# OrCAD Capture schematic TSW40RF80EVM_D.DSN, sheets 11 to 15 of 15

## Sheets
11 SHEET 12 - POWER SUPPLIES: size B; title: POWER SUPPLIES - CLOCK
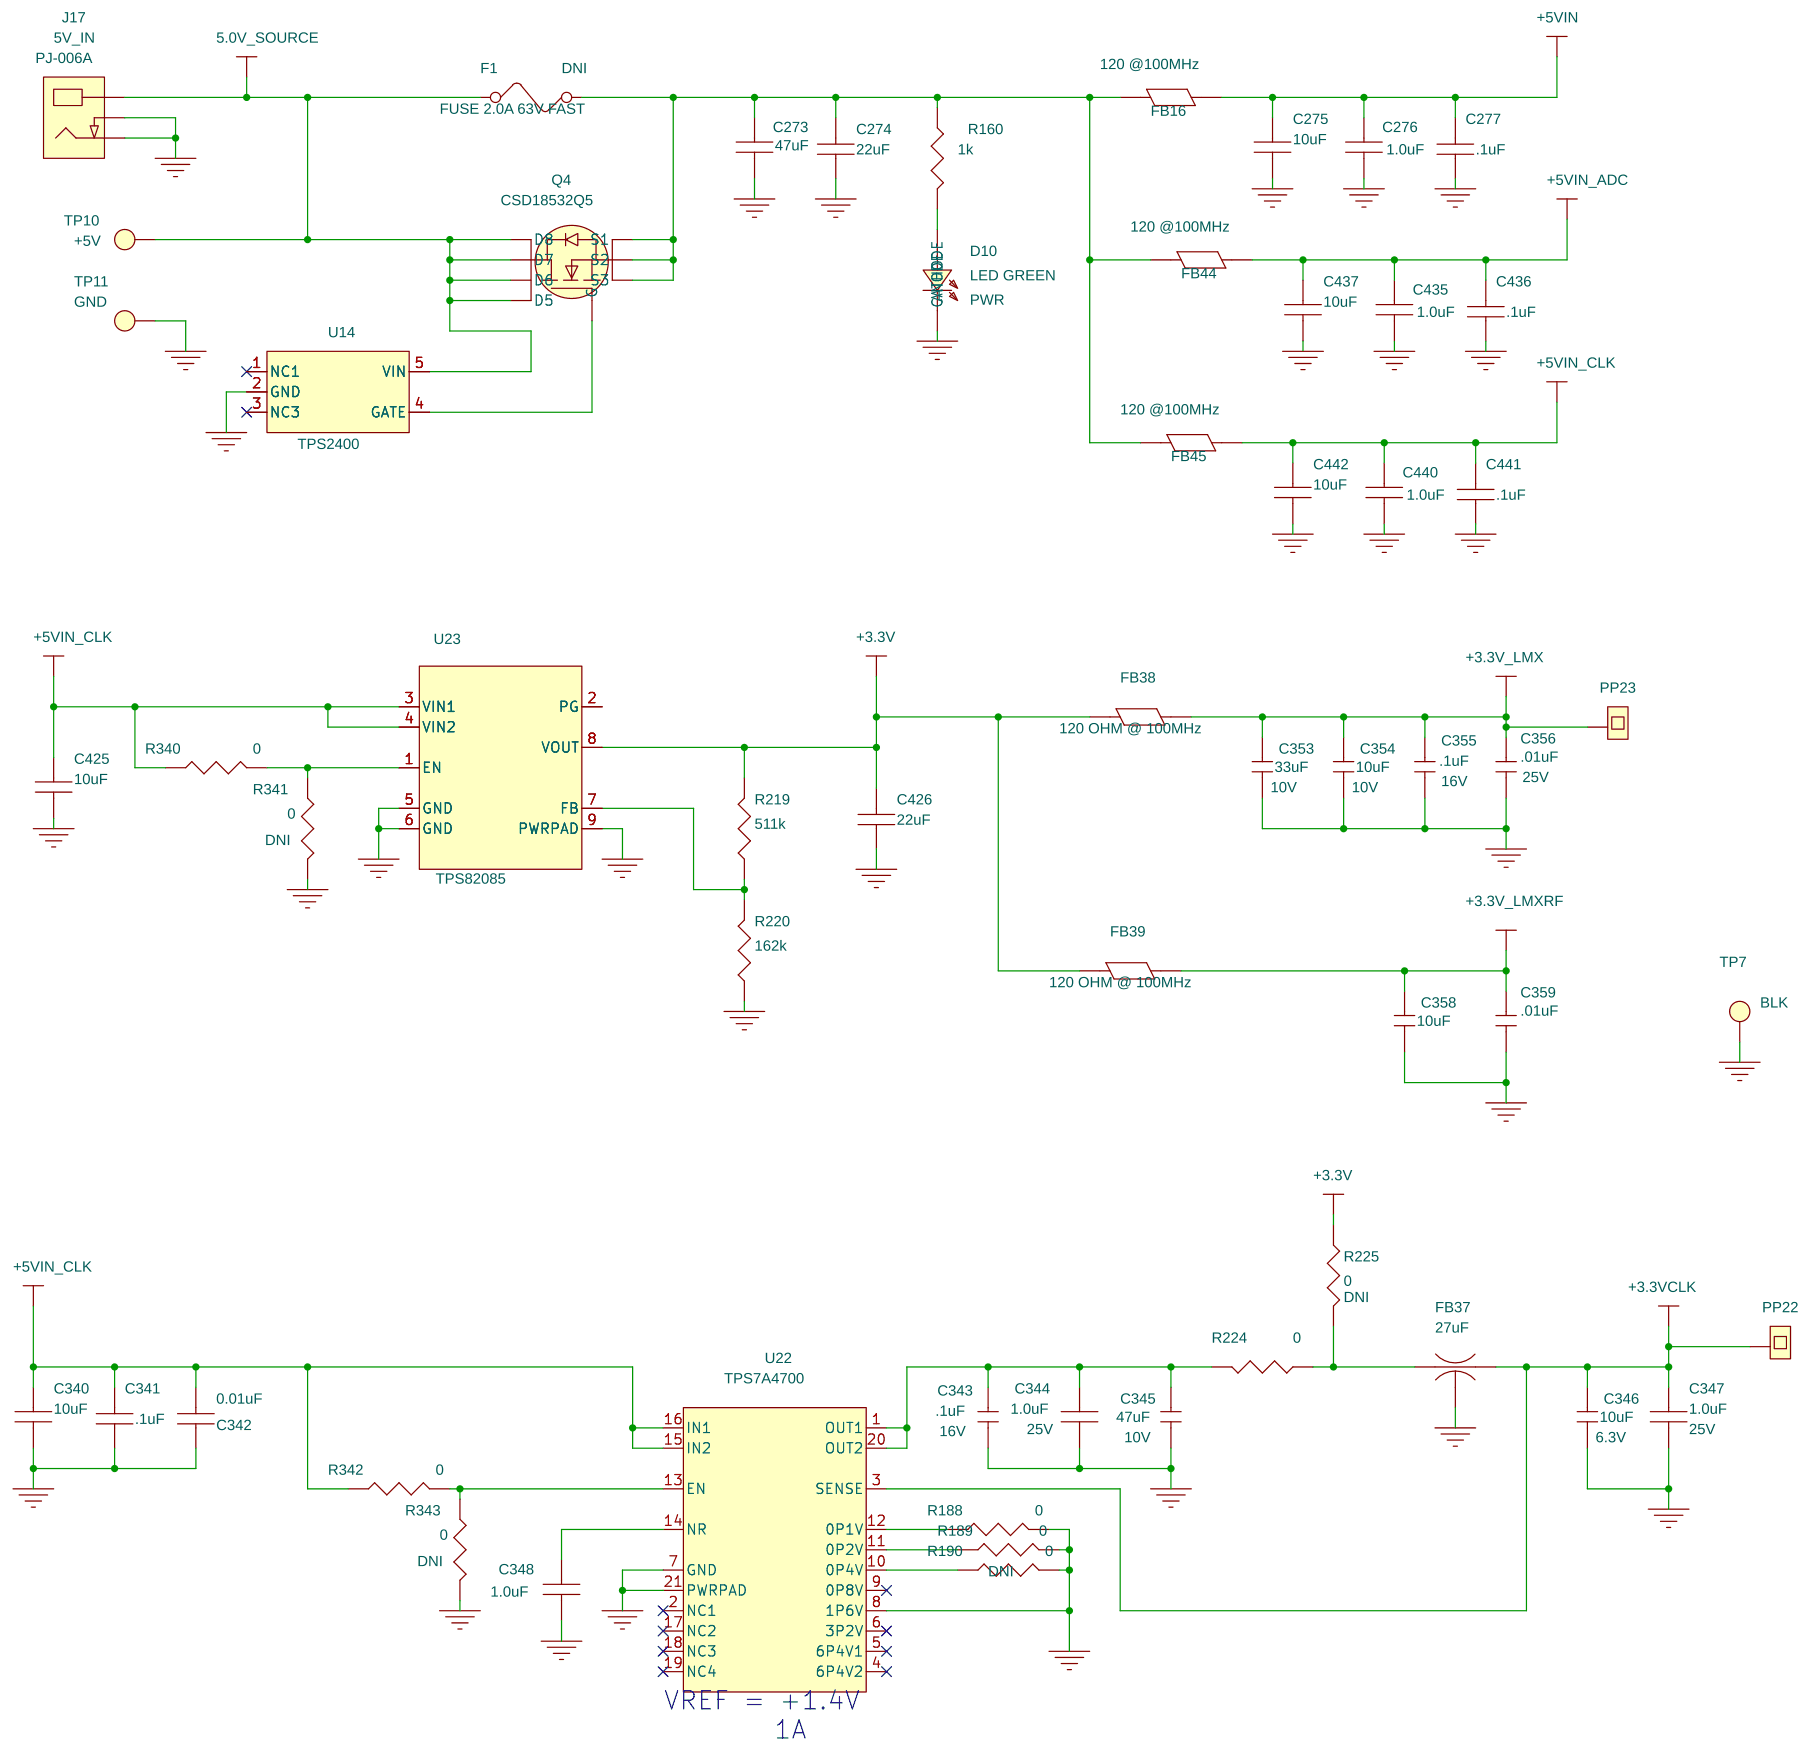
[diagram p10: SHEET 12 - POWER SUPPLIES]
12 SHEET 13 - POWER SUPPLIES: size B; title: POWER SUPPLIES - DAC
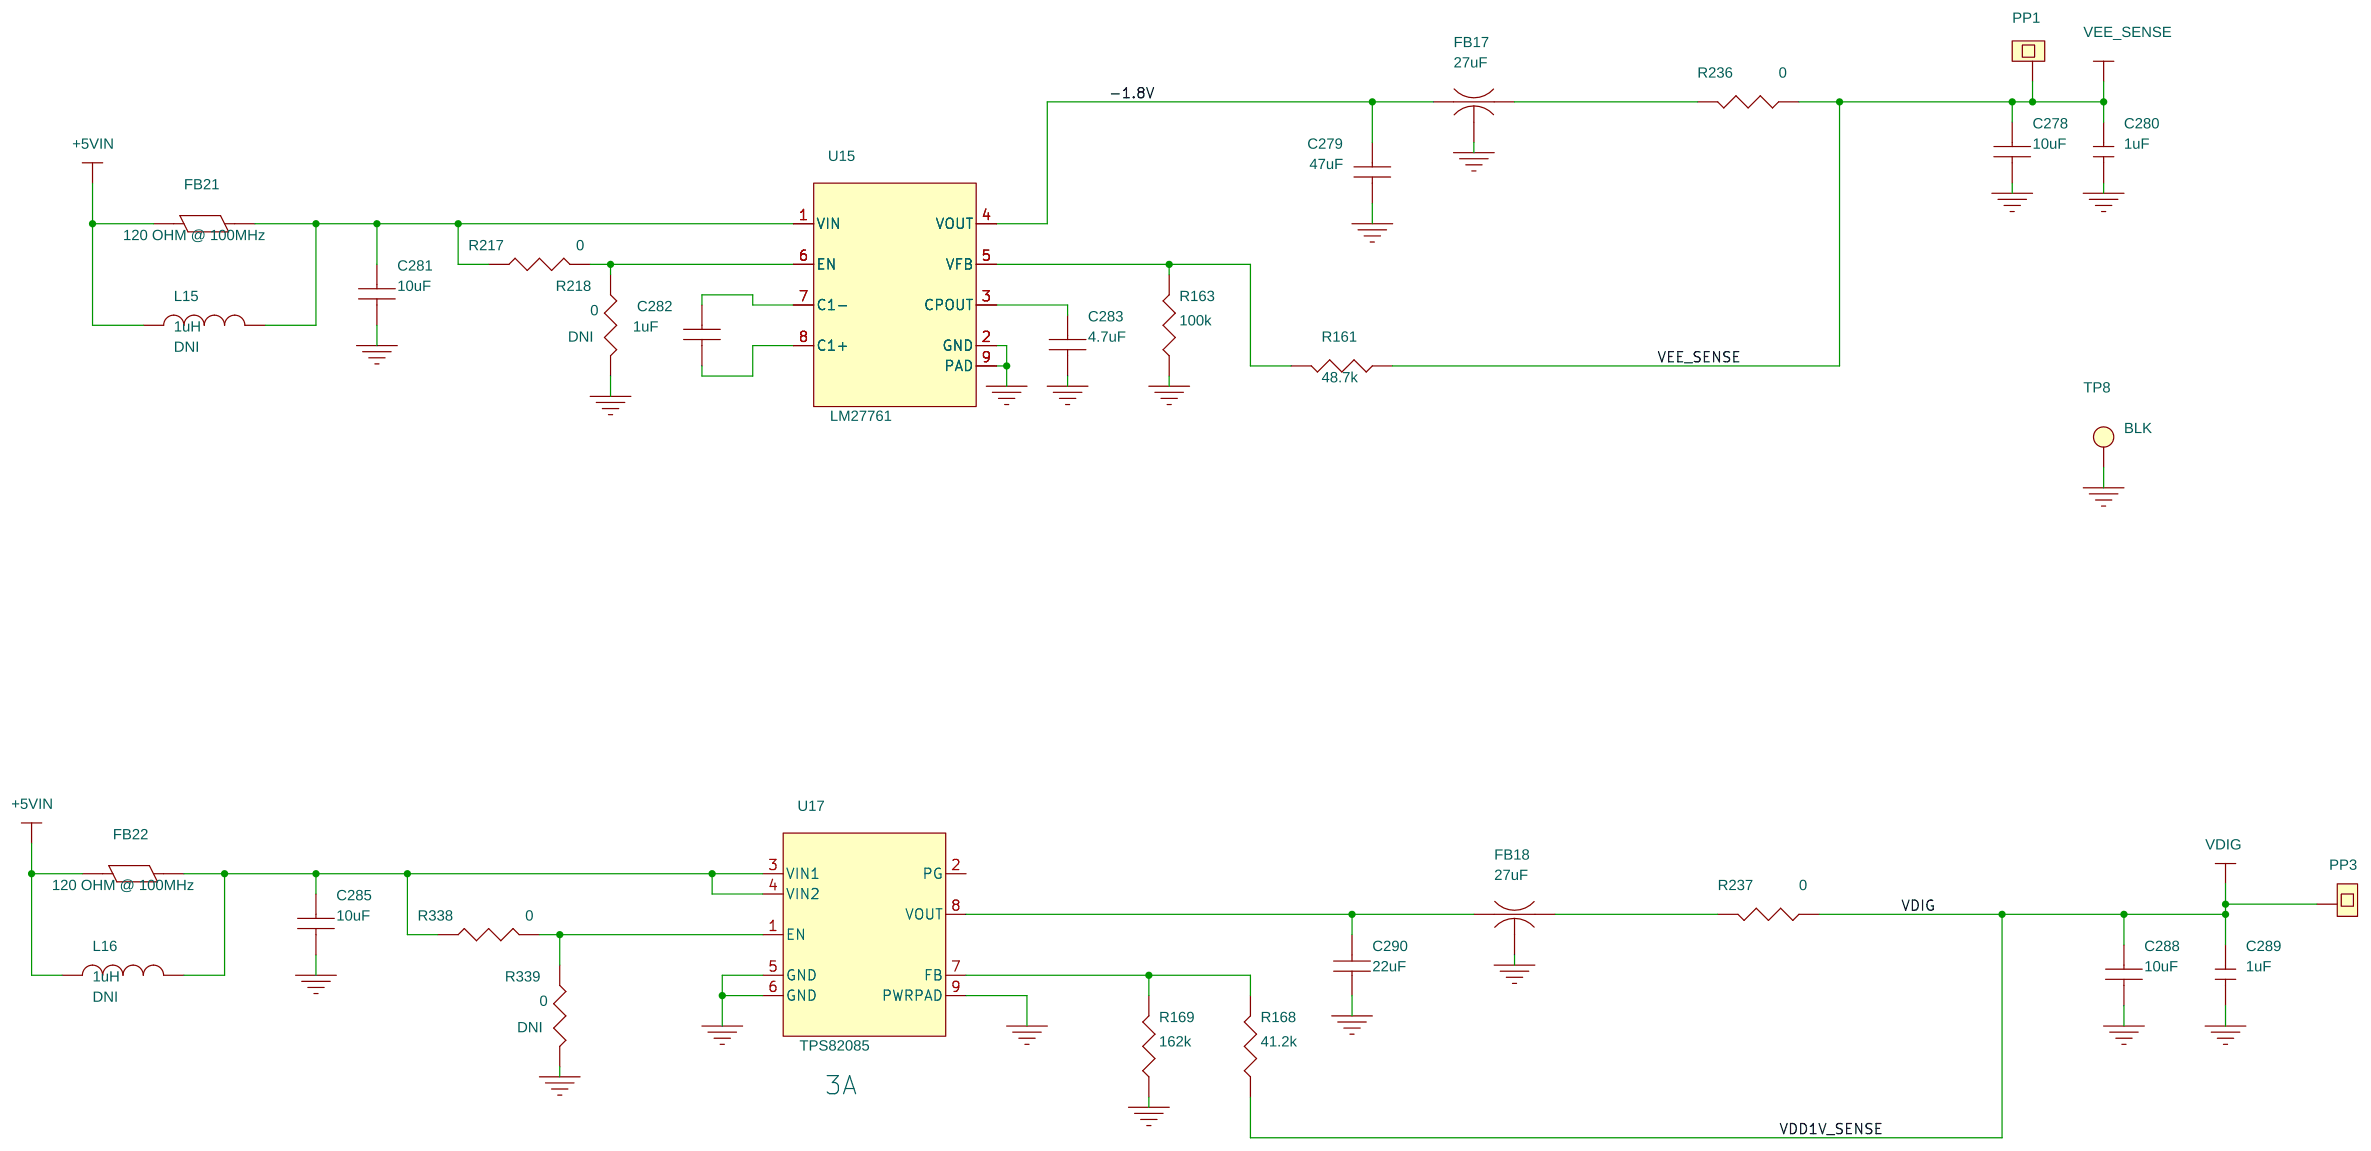
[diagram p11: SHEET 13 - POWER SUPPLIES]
13 SHEET 14 - POWER SUPPLIES: size B; title: POWER SUPPLIES - DAC
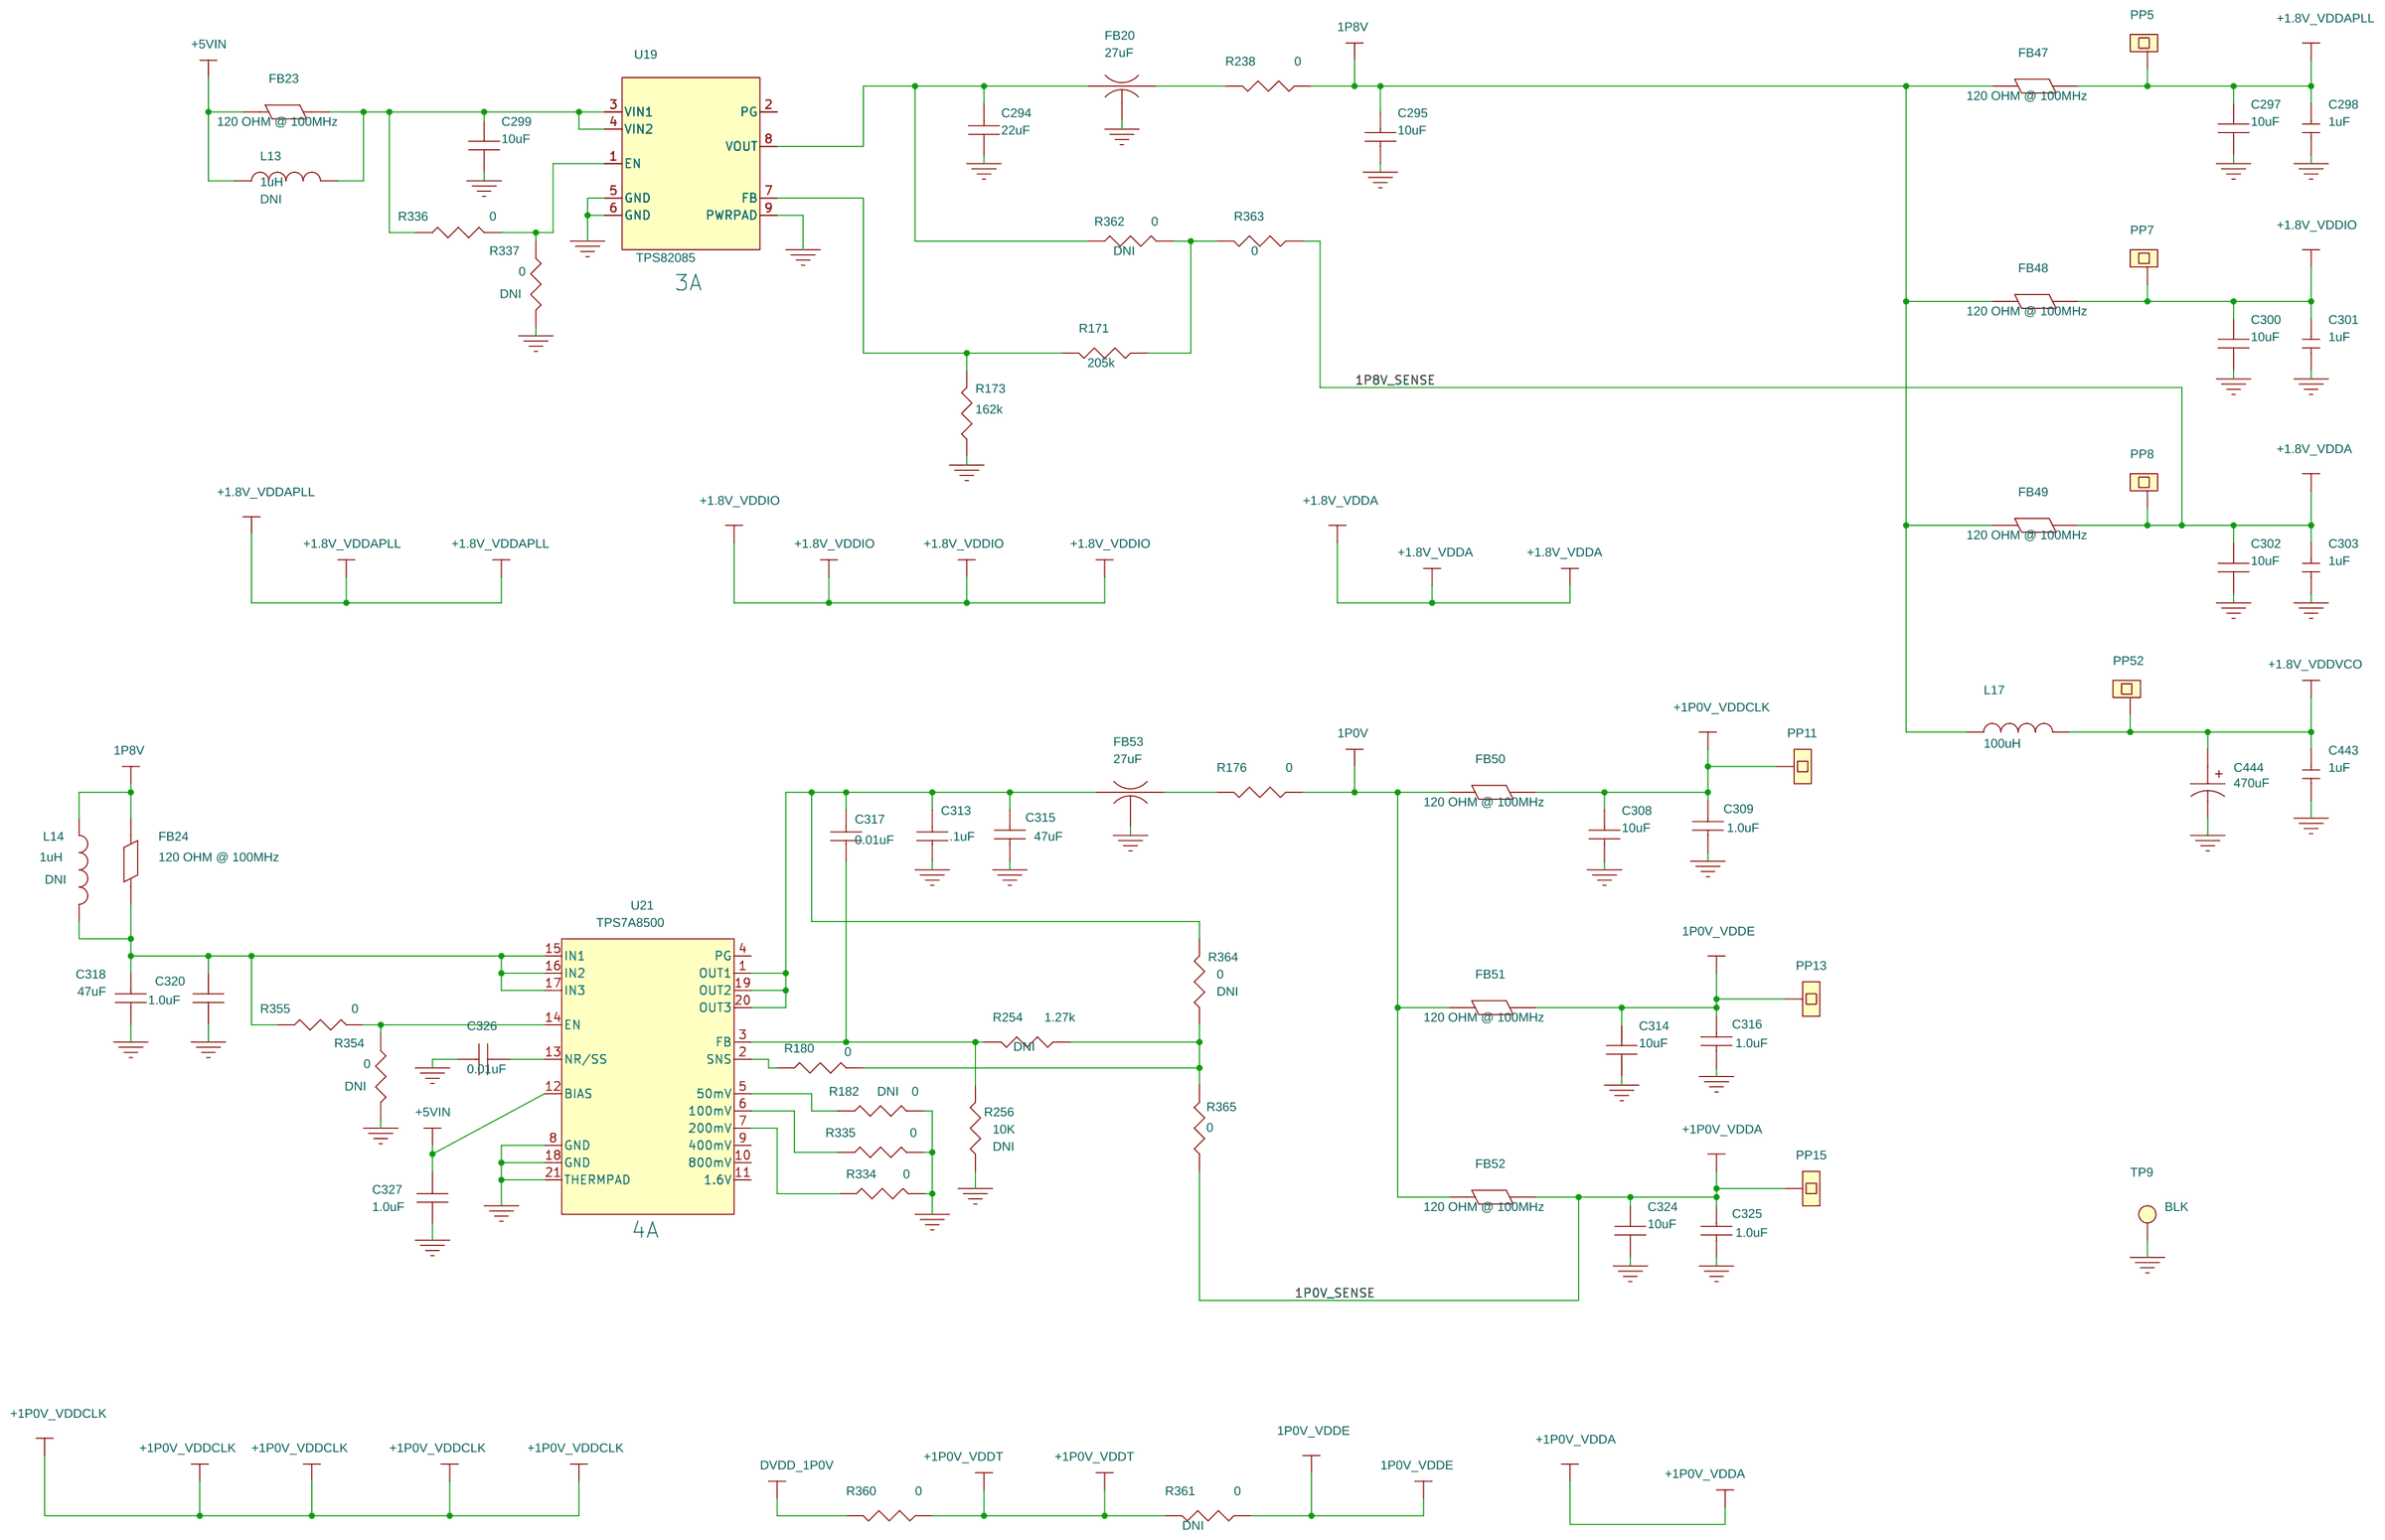
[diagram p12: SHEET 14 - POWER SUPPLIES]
14 SHEET 15 - POWER SUPPLIES: size B; title: POWER SUPPLIES - ADC
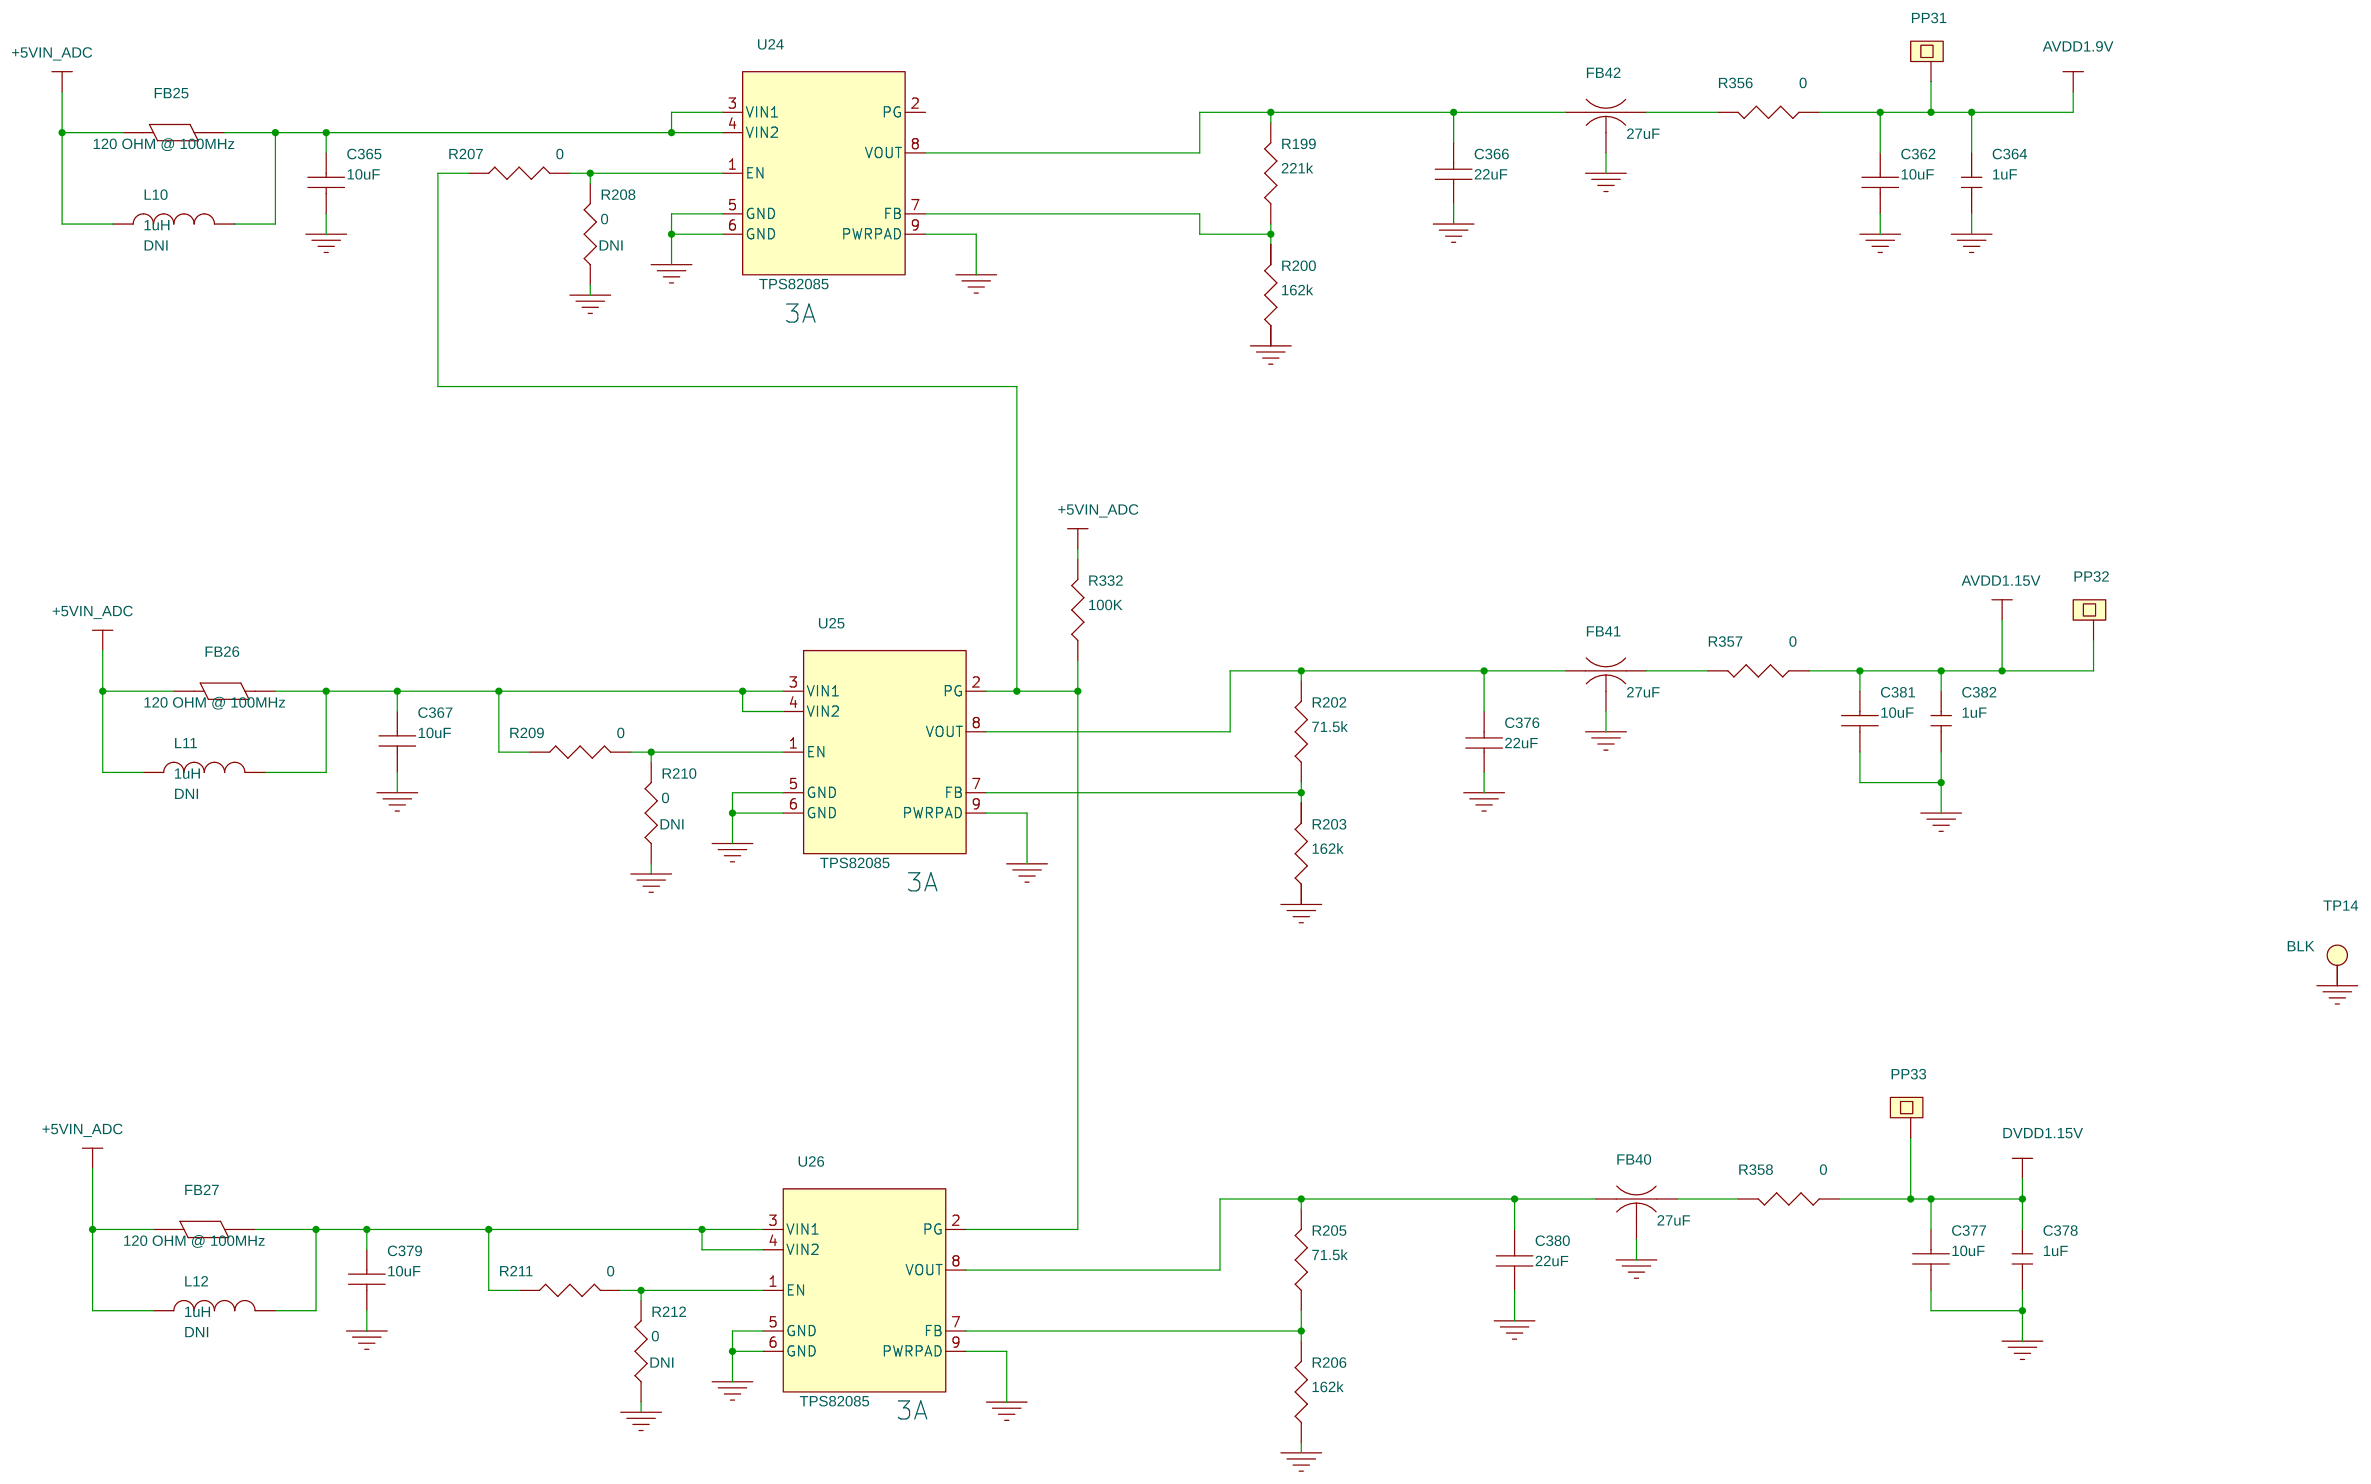
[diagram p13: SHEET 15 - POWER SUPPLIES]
15 SHEET 11 - USB I/F: size B; title: USB INTERFACE
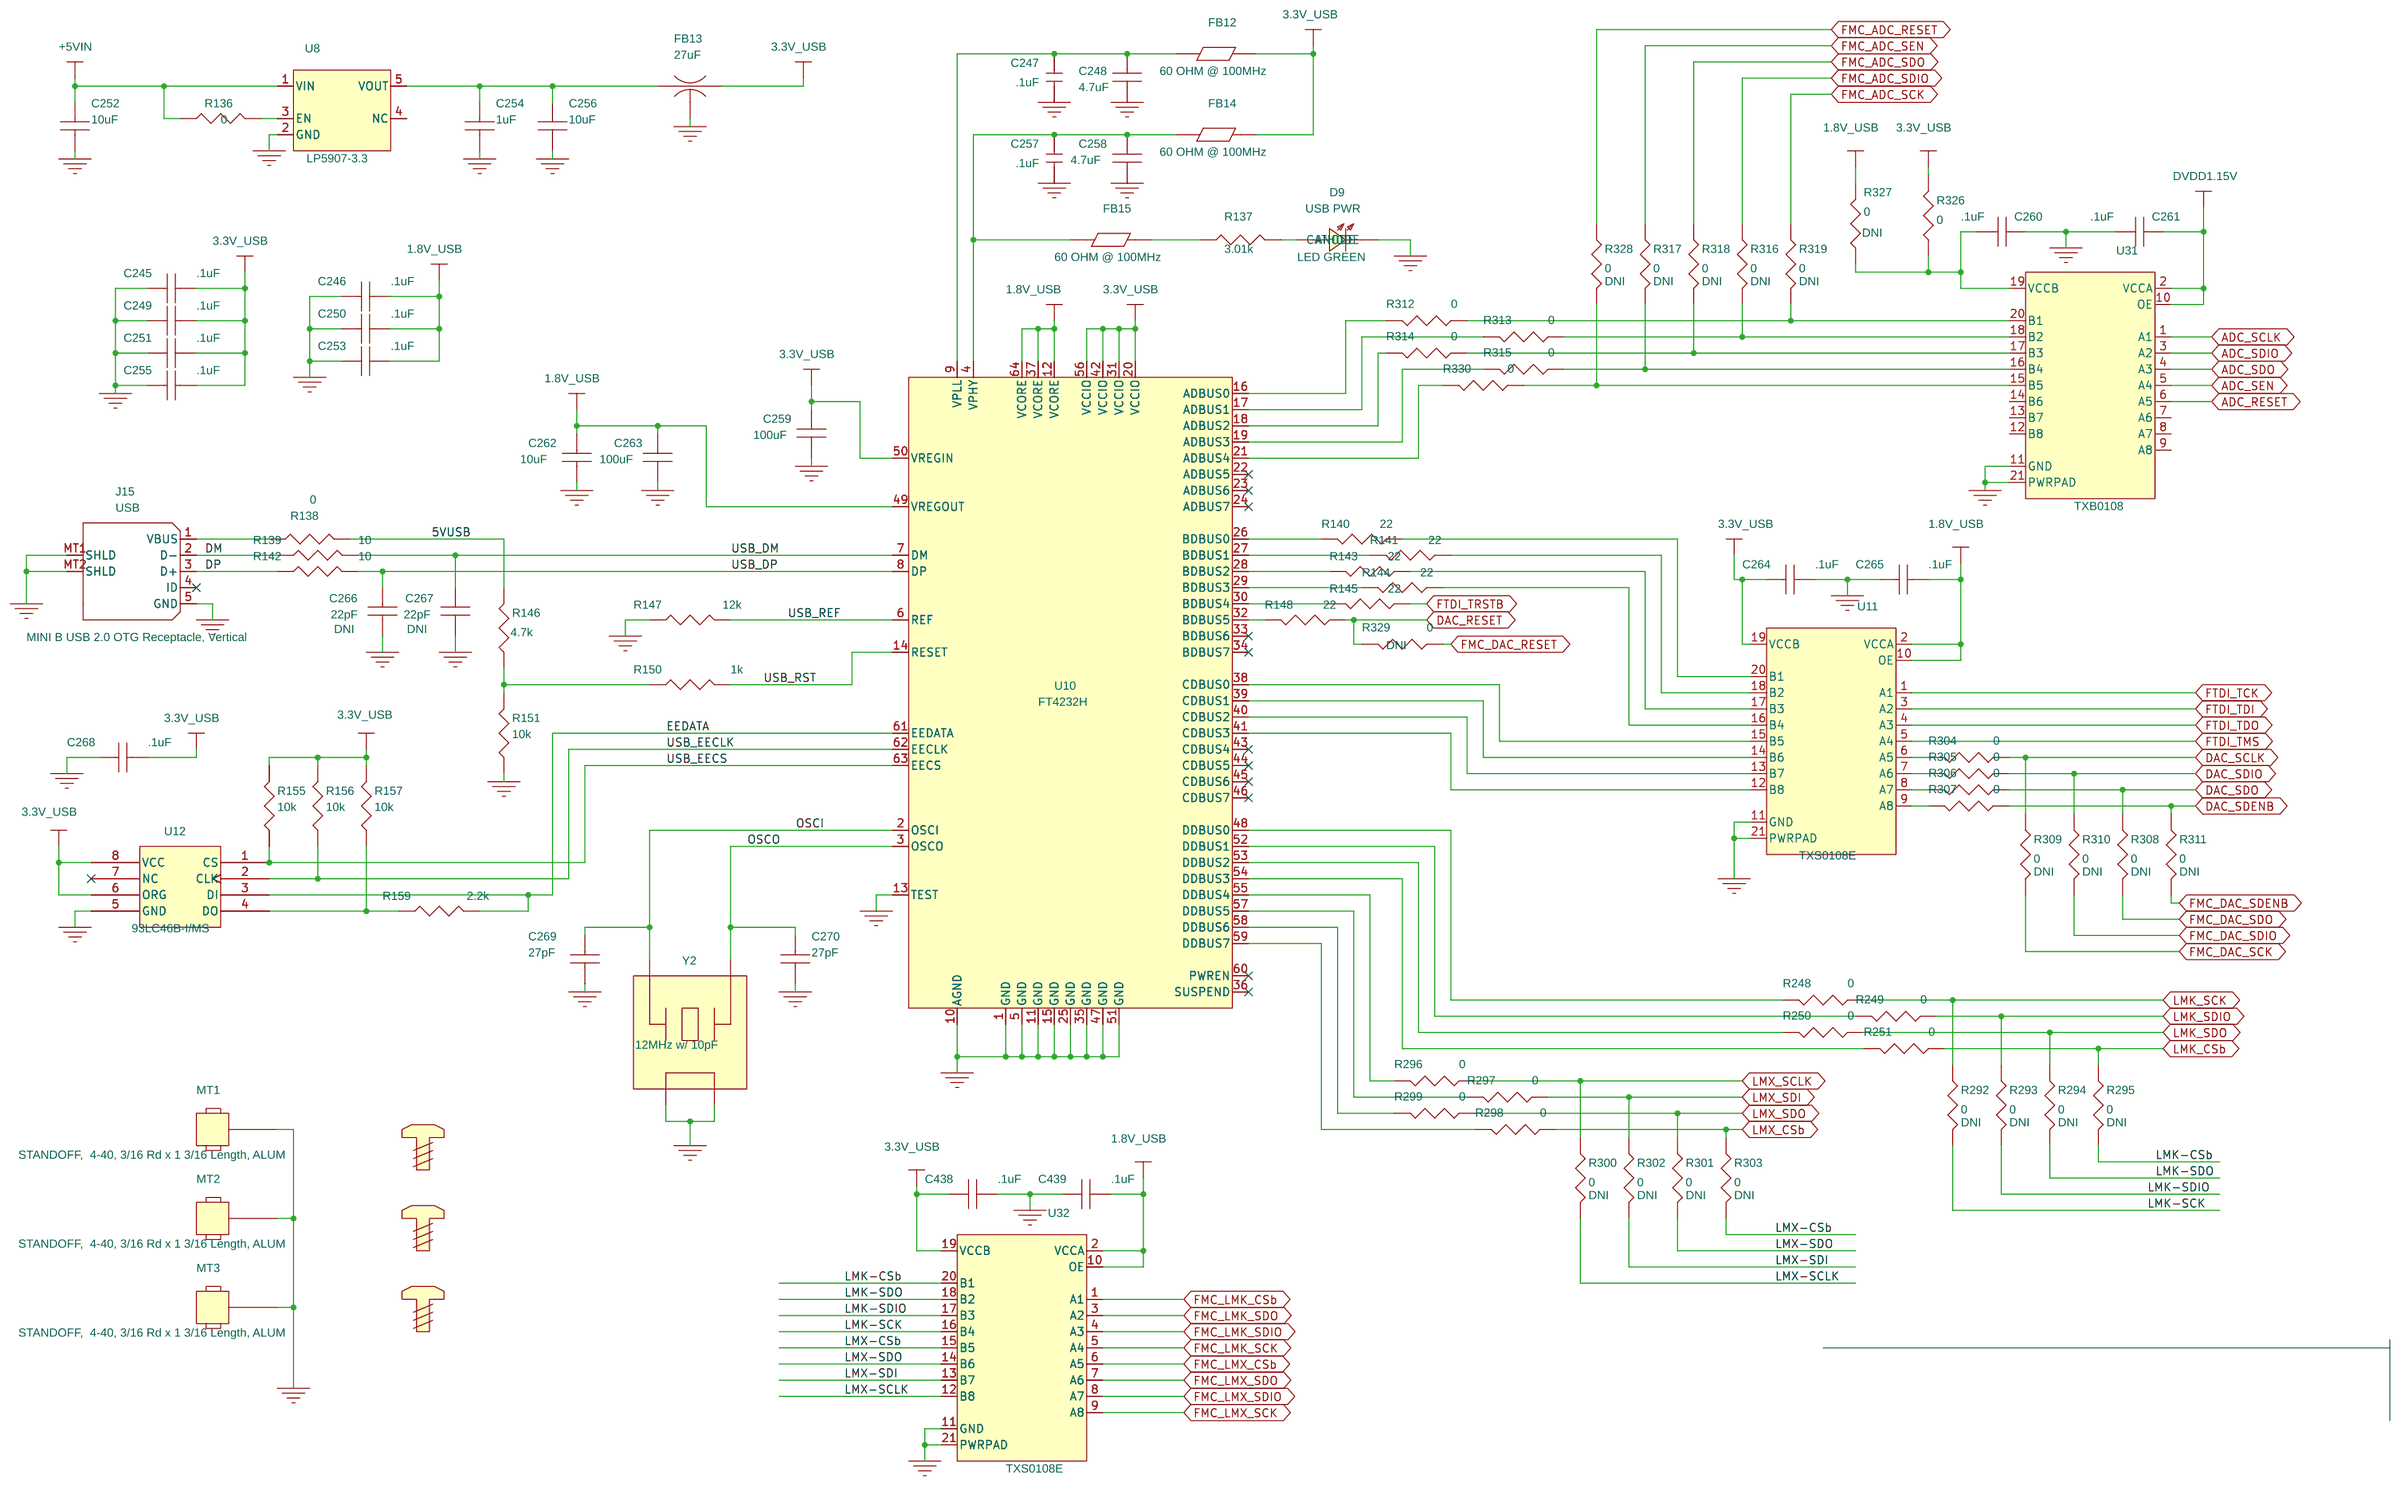
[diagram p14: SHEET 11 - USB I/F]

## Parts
sheet SHEET 11 - USB I/F
C245  .1uF  [0201]
C246  .1uF  [0201]
C247  .1uF  [0201]
C248  4.7uF  [0402]
C249  .1uF  [0201]
C250  .1uF  [0201]
C251  .1uF  [0201]
C252  10uF  [0402]
C253  .1uF  [0201]
C254  1uF  [0402]
C255  .1uF  [0201]
C256  10uF  [0402]
C257  .1uF  [0201]
C258  4.7uF  [0402]
C259  100uF  [1206]
C260  .1uF  [0201]
C261  .1uF  [0201]
C262  10uF  [0402]
C263  100uF  [1206]
C264  .1uF  [0201]
C265  .1uF  [0201]
C266  22pF  [0201]
C267  22pF  [0201]
C268  .1uF  [0201]
C269  27pF  [0201]
C270  27pF  [0201]
C438  .1uF  [0201]
C439  .1uF  [0201]
D9  LED GREEN  [LED_0603]
FB12  60 OHM @ 100MHz  [0603]
FB13  27uF  [1206_BEAD_NFM31P]
FB14  60 OHM @ 100MHz  [0603]
FB15  60 OHM @ 100MHz  [0603]
J15  MINI B USB 2.0 OTG Receptacle, Vertical  [CON_THVT_USBMINI_AB_F]
MT1  STANDOFF,  4-40, 3/16 Rd x 1 3/16 Length, ALUM  [MFG125_PLATED]
MT2  STANDOFF,  4-40, 3/16 Rd x 1 3/16 Length, ALUM  [MFG125_PLATED]
MT3  STANDOFF,  4-40, 3/16 Rd x 1 3/16 Length, ALUM  [MFG125_PLATED]
R136  0  [0402]
R137  3.01k  [0402]
R138  0  [0201]
R139  10  [0201]
R140  22  [0201]
R141  22  [0201]
R142  10  [0201]
R143  22  [0201]
R144  22  [0201]
R145  22  [0201]
R146  4.7k  [0201]
R147  12k  [0201]
R148  22  [0201]
R150  1k  [0201]
R151  10k  [0201]
R155  10k  [0201]
R156  10k  [0201]
R157  10k  [0201]
R159  2.2k  [0201]
R248  0  [0201]
R249  0  [0201]
R250  0  [0201]
R251  0  [0201]
R292  0  [0201]
R293  0  [0201]
R294  0  [0201]
R295  0  [0201]
R296  0  [0201]
R297  0  [0201]
R298  0  [0201]
R299  0  [0201]
R300  0  [0201]
R301  0  [0201]
R302  0  [0201]
R303  0  [0201]
R304  0  [0201]
R305  0  [0201]
R306  0  [0201]
R307  0  [0201]
R308  0  [0201]
R309  0  [0201]
R310  0  [0201]
R311  0  [0201]
R312  0  [0201]
R313  0  [0201]
R314  0  [0201]
R315  0  [0201]
R316  0  [0201]
R317  0  [0201]
R318  0  [0201]
R319  0  [0201]
R326  0  [0402]
R327  0  [0402]
R328  0  [0201]
R329  0  [0201]
R330  0  [0201]
U8  LP5907-3.3  [DBV5]
U10  FT4232H  [LQFP_64_402x402_20]
U11  TXS0108E  [QFN_20_183x144_RGY]
U12  93LC46B-I/MS  [MSOP_8_118X118_26]
U31  TXB0108  [QFN_20_183x144_RGY]
U32  TXS0108E  [QFN_20_183x144_RGY]
Y2  12MHz w/ 10pF  [XTAL_4_SM_130X102]
Z_SCREW1  SCREW, PHIL, 4-40x3/8", SS
Z_SCREW2  SCREW, PHIL, 4-40x3/8", SS
Z_SCREW3  SCREW, PHIL, 4-40x3/8", SS
sheet SHEET 12 - POWER SUPPLIES
C273  47uF  [1210]
C274  22uF  [1206]
C275  10uF  [0805]
C276  1.0uF  [0603]
C277  .1uF  [0402]
C340  10uF  [0805]
C341  .1uF  [0402]
C342  0.01uF  [0402]
C343  .1uF  [0402]
C344  1.0uF  [0603]
C345  47uF  [1210]
C346  10uF  [0805]
C347  1.0uF  [0603]
C348  1.0uF  [0603]
C353  33uF  [0805]
C354  10uF  [0603]
C355  .1uF  [0402]
C356  .01uF  [0201]
C358  10uF  [0603]
C359  .01uF  [0201]
C425  10uF  [0805]
C426  22uF  [0805]
C435  1.0uF  [0603]
C436  .1uF  [0402]
C437  10uF  [0805]
C440  1.0uF  [0603]
C441  .1uF  [0402]
C442  10uF  [0805]
D10  LED GREEN  [LED_1206]
F1  FUSE 2.0A 63V FAST  [1206]
FB16  120 @100MHz  [1206]
FB37  27uF  [1206_BEAD_NFM31P]
FB38  120 OHM @ 100MHz  [1206]
FB39  120 OHM @ 100MHz  [1206]
FB44  120 @100MHz  [1206]
FB45  120 @100MHz  [1206]
J17  PJ-006A  [JACK_THVT_3_520x343x421]
PP22  PROBE POINT  [PROBE_POINT_22PAD]
PP23  PROBE POINT  [PROBE_POINT_30PAD]
Q4  CSD18532Q5  [SON_Q5B_8]
R160  1k  [0402]
R188  0  [0402]
R189  0  [0402]
R190  0  [0402]
R219  511k  [0402]
R220  162k  [0402]
R224  0  [0805]
R225  0  [0805]
R340  0  [0402]
R341  0  [0402]
R342  0  [0402]
R343  0  [0402]
TP7  BLK  [TP_THVT_060_RND]
TP10  Testloop_Red  [testpoint_62dia]
TP11  Testloop_Black  [testpoint_62dia]
U14  TPS2400  [DBV5]
U22  TPS7A4700  [QFN_20_199x199_0p65mm]
U23  TPS82085  [uSIL_8_3MMx2p8MM_0p65mm]
sheet SHEET 13 - POWER SUPPLIES
C278  10uF  [0508]
C279  47uF  [0805]
C280  1uF  [0306]
C281  10uF  [0805]
C282  1uF  [0402]
C283  4.7uF  [0402]
C285  10uF  [0805]
C288  10uF  [0508]
C289  1uF  [0306]
C290  22uF  [0805]
FB17  27uF  [1206_BEAD_NFM31P]
FB18  27uF  [1206_BEAD_NFM31P]
FB21  120 OHM @ 100MHz  [1206]
FB22  120 OHM @ 100MHz  [1206]
L15  1uH  [IND_SM_142X189]
L16  1uH  [IND_SM_142X189]
PP1  PROBE POINT  [PROBE_POINT_30PAD]
PP3  PROBE POINT  [PROBE_POINT_30PAD]
R161  48.7k  [0402]
R163  100k  [0402]
R168  41.2k  [0402]
R169  162k  [0402]
R217  0  [0402]
R218  0  [0402]
R236  0  [0805]
R237  0  [0805]
R338  0  [0402]
R339  0  [0402]
TP8  BLK  [TP_THVT_060_RND]
U15  LM27761  [SON_DSG_8]
U17  TPS82085  [uSIL_8_3MMx2p8MM_0p65mm]
sheet SHEET 14 - POWER SUPPLIES
C294  22uF  [0805]
C295  10uF  [0805]
C297  10uF  [0508]
C298  1uF  [0306]
C299  10uF  [0805]
C300  10uF  [0508]
C301  1uF  [0306]
C302  10uF  [0508]
C303  1uF  [0306]
C308  10uF  [0805]
C309  1.0uF  [0603]
C313  .1uF  [0402]
C314  10uF  [0805]
C315  47uF  [0805]
C316  1.0uF  [0603]
C317  0.01uF  [0402]
C318  47uF  [0805]
C320  1.0uF  [0603]
C324  10uF  [0805]
C325  1.0uF  [0603]
C326  0.01uF  [0402]
C327  1.0uF  [0402]
C443  1uF  [0306]
C444  470uF  [7343]
FB20  27uF  [1206_BEAD_NFM31P]
FB23  120 OHM @ 100MHz  [1206]
FB24  120 OHM @ 100MHz  [1206]
FB47  120 OHM @ 100MHz  [1206]
FB48  120 OHM @ 100MHz  [1206]
FB49  120 OHM @ 100MHz  [1206]
FB50  120 OHM @ 100MHz  [1206]
FB51  120 OHM @ 100MHz  [1206]
FB52  120 OHM @ 100MHz  [1206]
FB53  27uF  [1206_BEAD_NFM31P]
L13  1uH  [IND_SM_142X189]
L14  1uH  [IND_SM_142X189]
L17  100uH  [IND_SM_110X138]
PP5  PROBE POINT  [PROBE_POINT_30PAD]
PP7  PROBE POINT  [PROBE_POINT_30PAD]
PP8  PROBE POINT  [PROBE_POINT_30PAD]
PP11  PROBE POINT  [PROBE_POINT_30PAD]
PP13  PROBE POINT  [PROBE_POINT_30PAD]
PP15  PROBE POINT  [PROBE_POINT_30PAD]
PP52  PROBE POINT  [PROBE_POINT_30PAD]
R171  205k  [0402]
R173  162k  [0402]
R176  0  [1206]
R180  0  [0402]
R182  0  [0402]
R238  0  [0805]
R254  1.27k  [0402]
R256  10K  [0402]
R334  0  [0402]
R335  0  [0402]
R336  0  [0402]
R337  0  [0402]
R354  0  [0402]
R355  0  [0402]
R360  0  [0805]
R361  0  [0805]
R362  0  [0402]
R363  0  [0402]
R364  0  [0402]
R365  0  [0402]
TP9  BLK  [TP_THVT_060_RND]
U19  TPS82085  [uSIL_8_3MMx2p8MM_0p65mm]
U21  TPS7A8500  [QFN20_RGR_p5mm]
sheet SHEET 15 - POWER SUPPLIES
C362  10uF  [0508]
C364  1uF  [0306]
C365  10uF  [0805]
C366  22uF  [0805]
C367  10uF  [0805]
C376  22uF  [0805]
C377  10uF  [0508]
C378  1uF  [0306]
C379  10uF  [0805]
C380  22uF  [0805]
C381  10uF  [0508]
C382  1uF  [0306]
FB25  120 OHM @ 100MHz  [1206]
FB26  120 OHM @ 100MHz  [1206]
FB27  120 OHM @ 100MHz  [1206]
FB40  27uF  [1206_BEAD_NFM31P]
FB41  27uF  [1206_BEAD_NFM31P]
FB42  27uF  [1206_BEAD_NFM31P]
L10  1uH  [IND_SM_142X189]
L11  1uH  [IND_SM_142X189]
L12  1uH  [IND_SM_142X189]
PP31  PROBE POINT  [PROBE_POINT_30PAD]
PP32  PROBE POINT  [PROBE_POINT_30PAD]
PP33  PROBE POINT  [PROBE_POINT_30PAD]
R199  221k  [0402]
R200  162k  [0402]
R202  71.5k  [0402]
R203  162k  [0402]
R205  71.5k  [0402]
R206  162k  [0402]
R207  0  [0402]
R208  0  [0402]
R209  0  [0402]
R210  0  [0402]
R211  0  [0402]
R212  0  [0402]
R332  100K  [0402]
R356  0  [0805]
R357  0  [0805]
R358  0  [0805]
TP14  BLK  [TP_THVT_060_RND]
U24  TPS82085  [uSIL_8_3MMx2p8MM_0p65mm]
U25  TPS82085  [uSIL_8_3MMx2p8MM_0p65mm]
U26  TPS82085  [uSIL_8_3MMx2p8MM_0p65mm]

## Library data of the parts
C245 C246 C249-C251 C253 C255 C260 C261 C264 C265 C268 C438 C439 = CAPACITOR_NP_1: Mfr_Name: MURATA; Mfr_Part_Number: GRM033R61A104KE15D; TOL: 10%; Voltage: 10V
C247 C257 = CAP0402_0: Mfr_Name: MURATA; Mfr_Part_Number: GRM033R61A104KE15D; TOL: 10%; Voltage: 10V
C248 C258 = CAP_NP_0: Mfr_Name: TDK; Mfr_Part_Number: C1005X5R1A475M050BC; TOL: 20%; VOLTAGE: 10V
C252 C256 = CAP_NP_1: Mfr_Name: SAMSUNG; Mfr_Part_Number: CL05A106MQ5NUNC; TOL: 20%; VOLTAGE: 6.3V
C254 C282 = CAP_NP_1: Mfr_Name: MURATA; Mfr_Part_Number: GRM155R61A105KE15D; TOL: 10%; VOLTAGE: 10V
C259 = CAP_1206: Mfr_Name: KEMET; Mfr_Part_Number: C1206C107M9PACTU
C262 = CAP_NP_1: CLASS: DISCRETE; Mfr_Name: SAMSUNG; Mfr_Part_Number: CL05A106MQ5NUNC; TOL: 20%; VOLTAGE: 6.3V
C263 = CAP_1206: Mfr_Name: TDK; Mfr_Part_Number: C3216X5R1A107M160AC
C266 C267 = CAP_NP: Mfr_Name: AVX; Mfr_Part_Number: GRM0335C1H220GA01D; Note: DNI; TOL: 2%; VOLTAGE: 50V
C269 C270 = CAP_NP: GROUP: NOT INSTALLED; Mfr_Name: Murata; Mfr_Part_Number: GRM0335C1E270JA01D; TOL: 5%; VOLTAGE: 25V
D9 = LED_AMBER_1206: Mfr_Name: Lite-On; Mfr_Part_Number: LTST-C191KGKT; TI_SILKTEXT: USB PWR
FB12 FB14 FB15 = FERRITE_BEAD: Mfr_Name: TDK; Mfr_Part_Number: MPZ1608S600ATAH0
FB13 FB17 FB18 FB20 FB37 FB40-FB42 FB53 = BEAD_NFM31P: Mfr_Name: Murata; Mfr_Part_Number: NFM31PC276B0J3L; Tolerance: 20%
J15 = USB_MINI_AB_VERT: Distributor Part Number: MNE20-5G5P10; Mfr_Name: Molex; Mfr_Part_Number: 5000751517; TI_SILKTEXT: USB
MT1-MT3 = MOUNTING_HOLE: Mfr_Name: RAF Electronic Hardware; Mfr_Part_Number: 1648-440-AL
R136 R180 R188 R189 R207 R209 R211 R217 R326 R334-R336 R338 R340 R342 R355 R363 R365 = R: Mfr_Name: Panasonic; Mfr_Part_Number: ERJ-2GE0R00X; TOL: 5%
R137 = R: Mfr_Name: PANASONIC; Mfr_Part_Number: ERJ-2RKF3011X; TOL: 5%; VOLTAGE: 1/16W
R138 = R: Mfr_Name: PANASONIC; Mfr_Part_Number: ERJ-1GN0R00C; TOL: 5%
R139 R142 = Res_0402_10_H: Mfr_Part_Number: ERJ-1GEF10R0C
R140 R141 R143-R145 R148 = Res_0402_10_H: Mfr_Part_Number: ERJ-1GEF22R0C
R146 = RESISTOR: 10K ohm, +/-1%, 1/16W(0402); Mfr_Name: PANASONIC; Mfr_Part_Number: ERJ-1GEF4701C; Package: SMD; Terasic_Prt: M0597; Type: Resistor
R147 = R: Mfr_Name: PANASONIC; Mfr_Part_Number: ERJ-1GEF1202C; TOL: 1%; Wattage: 1/20W
R150 = R_0: Mfr_Name: PANASONIC; Mfr_Part_Number: ERJ-1GEF1001C; TOL: 1%
R151 R155-R157 = R_0: CLASS: DISCRETE; Mfr_Name: PANASONIC; Mfr_Part_Number: ERJ-1GEF1002C; TOL: 1%
R159 = RESISTOR: 2.2K ohm, +/-1%, 1/16W(0402); Mfr_Name: Panasonic; Mfr_Part_Number: ERJ-1GEF2201C; Package: SMD; Terasic_Prt: M0733; Type: Resistor
R248-R251 R296-R299 R304-R307 R312-R315 R330 = Res_0402_10_H: Mfr_Part_Number: ERJ-1GN0R00C
R292-R295 R300-R303 R308-R311 R316-R319 R328 R329 = Res_0402_10_H: Mfr_Part_Number: ERJ-1GN0R00C; Note: DNI
R182 R190 R208 R210 R212 R218 R327 R337 R339 R341 R343 R354 R362 R364 = R: Mfr_Name: Panasonic; Mfr_Part_Number: ERJ-2GE0R00X; Note: DNI; TOL: 5%
U8 = LP5907: Mfr_Name: Texas Instruments; Mfr_Part_Number: LP5907MFX-3.3/NOPB
U10 = FT4232H_2: Mfr_Part_Number: FT4232HL-REEL
U11 U32 = TXS0108E
U12 = EEPROM: 93LC46B-I/SN,Serial EEPROM, 64 x 16bit, 2.5V-5.5V; Mfr_Name: Microchip; Package: SMD; Terasic_Prt: M0252
U31 = TXS0108E: Mfr_Part_Number: TXB0108RGYR
Y2 = CRYSTAL1-4_SM: Mfr_Name: Abracon; Mfr_Part_Number: ABM8G-12.000MHZ-B4Y-T
Z_SCREW1-Z_SCREW3 = STANDOFF-SCREW
C273 = CAP_NP_0: Mfr_Name: MURATA; Mfr_Part_Number: GRM32ER71A476KE15L; TOL: 10%; VOLTAGE: 10V
C274 = CAP_1210_22uF: Mfr_Name: MURATA; Mfr_Part_Number: GRM31CR71A226KE15L
C275 C295 C308 C314 C324 C437 C442 = CAP_NP_1: Mfr_Name: SAMSUNG; Mfr_Part_Number: CL21B106KOQNNNE; TOL: 10%; VOLTAGE: 16V
C276 C320 C348 C435 C440 = CAP_NP_0: Mfr_Name: TDK; Mfr_Part_Number: C1608X7R1E105K080AB; TOL: 10%; VOLTAGE: 25V
C277 C313 C341 C436 C441 = CAPACITOR_NP_1: Mfr_Name: MURATA; Mfr_Part_Number: GRM155R71C104KA88D; TOL: 10%; Voltage: 16V
C281 C285 C299 C340 C365 C367 C379 C425 = CAP_NP_1: Mfr_Name: MURATA; Mfr_Part_Number: GRM21BR61E106KA73L; TOL: 10%; VOLTAGE: 25V
C342 = CAPACITOR_NP_1: Mfr_Name: MURATA; Mfr_Part_Number: GRM155R71H103KA88D; TOL: 10%; Voltage: 16V
C343 C355 = CAP0603: Mfr_Name: MURATA; Mfr_Part_Number: GRM155R71C104KA88D; TOL: 10%; Voltage: 16V
C344 C347 = CAP_NP_1: Mfr_Name: TDK; Mfr_Part_Number: C1608X7R1E105K080AB; TOL: 10%; VOLTAGE: 25V
C345 = CAP0201_0: Mfr_Name: MURATA; Mfr_Part_Number: GRM32ER61A476KE20L; TOL: 10%; VOLTAGE: 10V
C346 = CAP0201_0: Mfr_Name: Murata; Mfr_Part_Number: GRM219R60J106KE19D; TOL: 20%; VOLTAGE: 6.3V
C353 = CAP0201_1: Mfr_Name: TDK; Mfr_Part_Number: C2012X5R1A336M125AC; TOL: 20%; VOLTAGE: 10V
C354 C358 = CAP0201_1: Mfr_Name: TDK; Mfr_Part_Number: C1608X5R1A106K080AC; TOL: 10%; VOLTAGE: 10V
C356 C359 = CAP0402_0: Mfr_Name: Murata; Mfr_Part_Number: GRM033R71A103KA01D; TOL: 10V; Voltage: 25V
C426 = CAP_1210_22uF: Mfr_Name: TDK; Mfr_Part_Number: C2012X5R1A226K125AB
D10 = LED_GREEN_1206: TI_SILKTEXT: PWR
F1 = FUSE_0: Mfr_Name: TE Connectivity; Mfr_Part_Number: 1206SFF200F/63-2; Note: DNI
FB16 FB44 FB45 = FERRITE_BEAD: Mfr_Name: Murata; Mfr_Part_Number: BLM31PG121SN1L
FB21-FB27 FB38 FB39 FB47-FB52 = FERRITE_BEAD_0402_H: Isat: 500mA; Mfr_Name: MURATA; Mfr_Part_Number: BLM31PG121SN1L
J17 = PWR_JACK_PJ006B: TI_SILKTEXT: 5V_IN; mfr_Name: CUI Inc
PP22 PP23 = PROBE_POINT_2: TI_Silktext: +3.3VCLK
Q4 = CSD18532Q5B: Mfr_Name: Texas Instruments
R160 = Res_0402_1k
R219 = Res_0603_Zero_H: Mfr_Part_Number: ERJ-2RKF5113X
R169 R173 R200 R203 R206 R220 = R: Mfr_Name: Panasonic; Mfr_Part_Number: ERJ-2RKF1623X; TOL: 1%
R224 R236-R238 R356-R358 R360 = Res_0402_Zero_H_DNI: Mfr_Name: KEYSTONE; Mfr_Part_Number: 5106
R225 R361 = Res_0402_Zero_H_DNI: Mfr_Name: KEYSTONE; Mfr_Part_Number: 5106; Note: DNI
TP7-TP9 = TESTPOINT_BLK
TP10 = TESTLOOP_BLACK: Mfr_Name: Keystone; Mfr_Part_Number: 5010; TI_SILKTEXT: +5V
TP11 = TESTLOOP_BLACK: Mfr_Name: KEYSTONE; Mfr_Part_Number: 5011; TI_SILKTEXT: GND
U14 = TPS2400: Mfr_Name: Texas Instruments; Mfr_Part_Number: TPS2400DBVT
U22 = TPS7A4700: Mfr_Name: Texas Instruments; Mfr_Part_Number: TPS7A4700RGWT
U17 U19 U23-U26 = TPS82085
C278 C288 C297 C300 C302 C362 C377 C381 = CAP_NP_1: Mfr_Name: Taiyo Yuden; Mfr_Part_Number: LWK212BJ106MD-T; TOL: 20%; VOLTAGE: 10V
C279 C318 = CAP_NP_1: Mfr_Name: TDK; Mfr_Part_Number: C2012X5R1A476M125AC; TOL: 10%; VOLTAGE: 10V
C280 C289 C298 C301 C303 C364 C378 C382 C443 = CAP0201_0: CLASS: DISCRETE; Mfr_Name: Samsung; Mfr_Part_Number: C0816X5R1C105M050AC; TOL: 20%; VOLTAGE: 16V
C283 = CAP_NP_1: Mfr_Name: TDK; Mfr_Part_Number: C1005X5R1A475K050BC; TOL: 10%; VOLTAGE: 10V
C290 C294 C366 C376 C380 = CAP_1210_22uF: Mfr_Name: TDK; Mfr_Part_Number: C2012X5R1A226K125AB; TOL: 10%; VOLTAGE: 10V
L10-L16 = CHOKE: Mfr_Name: Murata; Mfr_Part_Number: 84102C; Note: DNI
PP1 PP31-PP33 = PROBE_POINT_2: TI_Silktext: -1.8V_VEE
PP3 = PROBE_POINT_2: TI_Silktext: +0.9V_VDD
R161 = R: Mfr_Name: Panasonic; Mfr_Part_Number: ERJ-2RKF4872X; TOL: 1%
R163 R332 = R: Mfr_Name: Panasonic; Mfr_Part_Number: ERJ-2RKF1003X; TOL: 1%
R168 = Res_0603_Zero_H: Mfr_Part_Number: ERJ-2RKF4122X
U15 = LM27761: Mfr_Name: Texas Instruments; Mfr_Part_Number: LM27761DSGR
C309 C316 C325 = CAP_NP_0: Mfr_Name: Samsung Electro-Mechanics America, Inc; Mfr_Part_Number: CL10B105KO8NNNC; TOL: 10%; VOLTAGE: 16V
C315 = CAP_NP_0: Mfr_Name: TDK; Mfr_Part_Number: C2012X5R1A476M125AC; TOL: 10%; VOLTAGE: 10V
C317 C326 = CAP_NP_1: Mfr_Name: MURATA; Mfr_Part_Number: GRM155R71H103KA88D; TOL: 10%; VOLTAGE: 50V
C327 = CAPACITOR_NP_1: Mfr_Name: Murata; Mfr_Part_Number: GRM155R61A105KE15D; TOL: 10%; Voltage: 10V
C444 = CAPACITOR_POL: Mfr_Name: AVX; Mfr_Part_Number: TPSD477M006R0100; TOL: 20%; VOLTAGE: 6.3V
L17 = CHOKE: Mfr_Name: Coilcraft; Mfr_Part_Number: ME3220-104KLB
PP5 PP7 = PROBE_POINT_2: TI_Silktext: +1.8V_VDDVCO
PP8 PP52 = PROBE_POINT_2: TI_Silktext: +1.8V_VDDAPLL
PP11 = PROBE_POINT_0: TI_Silktext: +0.9V_VDDL1
PP13 = PROBE_POINT_0: TI_Silktext: +0.9V_VDDL2
PP15 = PROBE_POINT_0: TI_Silktext: +0.9V_VDDCLK
R171 = Res_0603_Zero_H: Mfr_Part_Number: ERJ-2RKF2053X
R176 = Res_0402_Zero_H_DNI: Mfr_Name: KEYSTONE; Mfr_Part_Number: 5108
R254 = R_0: Mfr_Name: PANASONIC; Mfr_Part_Number: ERJ-2RKF1271X; Note: DNI; TOL: 1%
R256 = RESISTOR: 10K ohm, +/-1%, 1/16W(0402); Mfr_Name: PANASONIC; Mfr_Part_Number: ERJ-2RKF1002X; Note: DNI; Package: SMD; TOL: 1%; Terasic_Prt: M0597; Type: Resistor
U21 = TPS7A8500
R199 = Res_0603_Zero_H: Mfr_Part_Number: ERJ-2RKF2213X
R202 R205 = Res_0603_Zero_H: Mfr_Part_Number: ERJ-2RKF7152X
TP14 = TESTPOINT_BLK: Manufacturer Part Number: 5001; Mfr_Name: Keystone; Mfr_Part_Number: 5001

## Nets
1.8V_USB: C246.2 C250.2 C253.2 C262.1 C263.1 C265.2 C439.2 R327.1 U10.12(VCORE) U10.37(VCORE) U10.49(VREGOUT) U10.64(VCORE) U11.2(VCCA) U11.10(OE) U32.2(VCCA) U32.10(OE)
3.3V_USB: C245.2 C249.2 C251.2 C255.2 C259.1 C264.1 C268.2 C438.1 FB12.1 FB13.3 FB14.1 R155.2 R156.2 R157.2 R326.1 U10.20(VCCIO) U10.31(VCCIO) U10.42(VCCIO) U10.50(VREGIN) U10.56(VCCIO) U11.19(VCCB) U12.6(ORG) U12.8(VCC) U32.19(VCCB)
5.0V_SOURCE: F1.1 J17.1 Q4.5(D5) Q4.6(D6) Q4.7(D7) Q4.8(D8) TP10.1(TP) U14.5(VIN)
5VUSB: R138.2 R146.1
+1.8V_ANA: C302.1 C303.1 FB49.2 PP8.1 R363.2 ; also on sheet 4
+1.8V_CLK: C297.1 C298.1 FB47.2 PP5.1 ; also on sheet 4
+1.8V_DIG: C300.1 C301.1 FB48.2 PP7.1 ; also on sheet 3 4
+1.8V_VDDVCO: C443.1 C444.1 L17.1 PP52.1 ; also on sheet 4
+3.3V: C426.2 FB38.1 FB39.1 R219.1 R225.1 U23.8(VOUT)
+3.3V_LMX: C353.1 C354.1 C355.1 C356.1 FB38.2 PP23.1 ; also on sheet 7
+3.3V_LMXRF: C358.1 C359.1 FB39.2 ; also on sheet 5 7
+3.3VCLK: C346.1 C347.1 FB37.3 PP22.1 U22.3(SENSE) ; also on sheet 8 9
+5VIN: C252.1 C275.1 C276.1 C277.2 C327.2 FB16.1 FB21.1 FB22.1 FB23.1 L13.1 L15.1 L16.1 R136.2 U8.1(VIN) U21.12(BIAS) ; also on sheet 6 10
+5VIN_ADC: C435.1 C436.2 C437.1 FB25.1 FB26.1 FB27.1 FB44.1 L10.1 L11.1 L12.1 R332.1
+5VIN_CLK: C340.1 C341.2 C342.2 C425.1 C440.1 C441.2 C442.1 FB45.1 R340.2 R342.2 U22.15(IN2) U22.16(IN1) U23.3(VIN1) U23.4(VIN2)
-1.8V: C279.1 FB17.1 U15.4(VOUT)
-1.8V_VEE: C278.1 C280.1 PP1.1 R161.2 R236.1 ; also on sheet 4
AVDD1.9V: C362.1 C364.1 PP31.1 R356.1 ; also on sheet 6
AVDD1.15V: C381.1 C382.1 PP32.1 R357.1 ; also on sheet 6
DVDD1.15V: C261.1 C377.1 C378.1 PP33.1 R358.1 U31.2(VCCA) U31.10(OE) ; also on sheet 6
DVDD_1P0V: C288.1 C289.1 PP3.1 R168.2 R237.1 R360.2 ; also on sheet 4
GND: C245.1 C246.1 C247.2 C248.2 C249.1 C250.1 C251.1 C252.2 C253.1 C254.2 C255.1 C256.2 C257.2 C258.2 C259.2 C260.1 C261.2 C262.2 C263.2 C264.2 C265.1 C266.2 C267.2 C268.1 C269.2 C270.2 C273.2 C274.1 C275.2 C276.2 C277.1 C278.2 C279.2 C280.2 C281.2 C283.2 C285.2 C288.2 C289.2 C290.1 C294.1 C295.2 C297.2 C298.2 C299.2 C300.2 C301.2 C302.2 C303.2 C308.2 C309.2 C313.1 C314.2 C315.2 C316.2 C318.2 C320.2 C324.2 C325.2 C326.1 C327.1 C340.2 C341.1 C342.1 C343.2 C344.2 C345.2 C346.2 C347.2 C348.2 C353.2 C354.2 C355.2 C356.2 C358.2 C359.2 C362.2 C364.2 C365.2 C366.1 C367.2 C376.1 C377.2 C378.2 C379.2 C380.1 C381.2 C382.2 C425.2 C426.1 C435.2 C436.1 C437.2 C438.2 C439.1 C440.2 C441.1 C442.2 C443.2 C444.2 D9.2(CATHODE) D10.2(CATHODE) FB13.2 FB17.2 FB18.2 FB20.2 FB37.2 FB40.2 FB41.2 FB42.2 FB53.2 J15.5(GND) J15.MT1(SHLD) J15.MT2(SHLD) J17.2 J17.3 MT1.1 MT2.1 MT3.1 R147.2 R151.1 R163.2 R169.2 R173.2 R182.1 R188.1 R189.1 R190.1 R200.2 R203.2 R206.2 R208.2 R210.2 R212.2 R218.2 R220.2 R256.2 R334.1 R335.1 R337.2 R339.2 R341.2 R343.2 R354.2 TP7.1(TP) TP8.1(TP) TP9.1(TP) TP11.1(TP) TP14.1(TP) U8.2(GND) U10.1(GND) U10.5(GND) U10.10(AGND) U10.11(GND) U10.13(TEST) U10.15(GND) U10.25(GND) U10.35(GND) U10.47(GND) U10.51(GND) U11.11(GND) U11.21(PWRPAD) U12.5(GND) U14.2(GND) U15.2(GND) U15.9(PAD) U17.5(GND) U17.6(GND) U17.9(PWRPAD) U19.5(GND) U19.6(GND) U19.9(PWRPAD) U21.8(GND) U21.18(GND) U21.21(THERMPAD) U22.7(GND) U22.8(1P6V) U22.21(PWRPAD) U23.5(GND) U23.6(GND) U23.9(PWRPAD) U24.5(GND) U24.6(GND) U24.9(PWRPAD) U25.5(GND) U25.6(GND) U25.9(PWRPAD) U26.5(GND) U26.6(GND) U26.9(PWRPAD) U31.11(GND) U31.21(PWRPAD) U32.11(GND) U32.21(PWRPAD) Y2.2 Y2.4 ; also on sheet 2 3 4 5 6 7 8 9 10
1P0V: FB50.1 FB51.1 FB52.1 R176.1
1P8V: C295.1 FB24.2 FB47.1 FB48.1 FB49.1 L14.2 L17.2 R238.1
+1P0V_ANA: C324.1 C325.1 FB52.2 PP15.1 R365.2 ; also on sheet 4
+1P0V_CLK: C308.1 C309.1 FB50.2 PP11.1 ; also on sheet 4
+1P0V_DIG: C314.1 C316.1 FB51.2 PP13.1 R361.1 ; also on sheet 4
+1P0V_VDDL1: R360.1 R361.2 ; also on sheet 4
ADC_RESET: U31.6(A5) ; also on sheet 6
ADC_SCLK: U31.1(A1) ; also on sheet 6
ADC_SDIO: U31.3(A2) ; also on sheet 6
ADC_SDO: U31.4(A3) ; also on sheet 6
ADC_SEN: U31.5(A4) ; also on sheet 6
DAC_RESET: R148.1 R329.2 ; also on sheet 3
DAC_SCLK: R304.1 R309.1 ; also on sheet 3
DAC_SDENB: R307.1 R311.1 ; also on sheet 3
DAC_SDIO: R305.1 R310.1 ; also on sheet 3
DAC_SDO: R306.1 R308.1 ; also on sheet 3
DM: J15.2(D-) R139.1
DP: J15.3(D+) R142.1
EEDATA: R159.1 U10.61(EEDATA) U12.3(DI)
FMC_ADC_RESET: R328.1 ; also on sheet 10
FMC_ADC_SCK: R319.1 ; also on sheet 10
FMC_ADC_SDIO: R316.1 ; also on sheet 10
FMC_ADC_SDO: R318.1 ; also on sheet 10
FMC_ADC_SEN: R317.1 ; also on sheet 10
FMC_DAC_RESET: R329.1 ; also on sheet 10
FMC_DAC_SCK: R309.2 ; also on sheet 10
FMC_DAC_SDENB: R311.2 ; also on sheet 10
FMC_DAC_SDIO: R310.2 ; also on sheet 10
FMC_DAC_SDO: R308.2 ; also on sheet 10
FMC_LMK_CSb: U32.1(A1) ; also on sheet 10
FMC_LMK_SCK: U32.5(A4) ; also on sheet 10
FMC_LMK_SDIO: U32.4(A3) ; also on sheet 10
FMC_LMK_SDO: U32.3(A2) ; also on sheet 10
FMC_LMX_CSb: U32.6(A5) ; also on sheet 10
FMC_LMX_SCK: U32.9(A8) ; also on sheet 10
FMC_LMX_SDIO: U32.8(A7) ; also on sheet 10
FMC_LMX_SDO: U32.7(A6) ; also on sheet 10
FTDI_TCK: U11.1(A1) ; also on sheet 3
FTDI_TDI: U11.3(A2) ; also on sheet 3
FTDI_TDO: U11.4(A3) ; also on sheet 3
FTDI_TMS: U11.5(A4) ; also on sheet 3
FTDI_TRSTB: R145.1 ; also on sheet 3
LMK-CSb: R295.2 U32.20(B1)
LMK-SCK: R292.2 U32.16(B4)
LMK-SDIO: R293.2 U32.17(B3)
LMK-SDO: R294.2 U32.18(B2)
LMK_CSb: R251.1 R295.1 ; also on sheet 9
LMK_SCK: R248.1 R292.1 ; also on sheet 9
LMK_SDIO: R249.1 R293.1 ; also on sheet 9
LMK_SDO: R250.1 R294.1 ; also on sheet 9
LMX-CSb: R303.2 U32.15(B5)
LMX-SCLK: R300.2 U32.12(B8)
LMX-SDI: R302.2 U32.13(B7)
LMX-SDO: R301.2 U32.14(B6)
LMX_CSb: R298.1 R303.1 ; also on sheet 7
LMX_SCLK: R296.1 R300.1 ; also on sheet 7
LMX_SDI: R297.1 R302.1 ; also on sheet 7
LMX_SDO: R299.1 R301.1 ; also on sheet 7
OSCI: C269.1 U10.2(OSCI) Y2.1
OSCO: C270.1 U10.3(OSCO) Y2.3
USB_DM: C267.1 R139.2 U10.7(DM)
USB_DP: C266.1 R142.2 U10.8(DP)
USB_EECLK: R156.1 U10.62(EECLK) U12.2(CLK)
USB_EECS: R155.1 U10.63(EECS) U12.1(CS)
USB_REF: R147.1 U10.6(REF)
USB_RST: R150.2 U10.14(RESET)
N16791764: J15.1(VBUS) R138.1
N16791900: C257.1 C258.1 FB14.2 FB15.2 U10.4(VPHY)
N16791904: C247.1 C248.1 FB12.2 U10.9(VPLL)
N16792068: R146.2 R150.1 R151.2
N16792392: R157.1 R159.2 U12.4(DO)
N17033323: FB15.1 R137.1
N17033325: D9.1(ANODE) R137.2
N17828171: C254.1 C256.1 FB13.1 U8.5(VOUT)
N17829143: R136.1 U8.3(EN)
N18967863: FB17.3 R236.2
N19402254: R251.2 U10.54(DDBUS3)
N19402263: R250.2 U10.53(DDBUS2)
N19402272: R249.2 U10.52(DDBUS1)
N19402281: R248.2 U10.48(DDBUS0)
N19909006: C290.2 FB18.1 U17.8(VOUT)
N20098160: R312.2 U10.16(ADBUS0)
N20098174: C260.2 R326.2 R327.2 U31.19(VCCB)
N20098233: R313.2 U10.17(ADBUS1)
N20098235: R314.2 U10.18(ADBUS2)
N20098237: R315.2 U10.19(ADBUS3)
N20101383: R144.1 U11.16(B4)
N20101387: R143.1 U11.17(B3)
N20101391: R141.1 U11.18(B2)
N20101395: R140.1 U11.20(B1)
N20101461: U10.41(CDBUS3) U11.12(B8)
N20101463: U10.40(CDBUS2) U11.13(B7)
N20101465: U10.39(CDBUS1) U11.14(B6)
N20101467: U10.38(CDBUS0) U11.15(B5)
N20101487: R148.2 U10.32(BDBUS5)
N20101489: R145.2 U10.30(BDBUS4)
N20101501: R141.2 U10.27(BDBUS1)
N20101503: R144.2 U10.29(BDBUS3)
N20101505: R140.2 U10.26(BDBUS0)
N20101507: R143.2 U10.28(BDBUS2)
N20119510: C282.1 U15.7(C1-)
N20119513: C282.2 U15.8(C1+)
N20119835: C283.1 U15.3(CPOUT)
N20120157: R161.1 R163.1 U15.5(VFB)
N20121909: R168.1 R169.1 U17.7(FB)
N20122077: C285.1 FB22.2 L16.2 R338.2 U17.3(VIN1) U17.4(VIN2)
N20122091: R338.1 R339.1 U17.1(EN)
N20123661: C294.2 FB20.1 R362.2 U19.8(VOUT)
N20123671: C299.1 FB23.2 L13.2 R336.2 U19.3(VIN1) U19.4(VIN2)
N20123702: R171.1 R173.1 U19.7(FB)
N20123718: R336.1 R337.1 U19.1(EN)
N20123815: FB20.3 R238.2
N20149572: R297.2 U10.57(DDBUS5)
N20149573: R296.2 U10.55(DDBUS4)
N20149574: R299.2 U10.58(DDBUS6)
N20149575: R298.2 U10.59(DDBUS7)
N20275378: FB42.3 R356.2
N20275382: C366.2 FB42.1 R199.1 U24.8(VOUT)
N20275455: C365.1 FB25.2 L10.2 U24.3(VIN1) U24.4(VIN2)
N20275475: R199.2 R200.1 U24.7(FB)
N20275808: C376.2 FB41.1 R202.1 U25.8(VOUT)
N20275812: C367.1 FB26.2 L11.2 R209.2 U25.3(VIN1) U25.4(VIN2)
N20275835: R202.2 R203.1 U25.7(FB)
N20276430: C380.2 FB40.1 R205.1 U26.8(VOUT)
N20276536: FB40.3 R358.2
N20276599: C379.1 FB27.2 L12.2 R211.2 U26.3(VIN1) U26.4(VIN2)
N20276622: R205.2 R206.1 U26.7(FB)
N20276940: FB41.3 R357.2
N20277804: R207.2 R332.2 U25.2(PG) U26.2(PG)
N20277812: R207.1 R208.1 U24.1(EN)
N20277928: R209.1 R210.1 U25.1(EN)
N20285160: C343.1 C344.1 C345.1 R224.2 U22.1(OUT1) U22.20(OUT2)
N20285162: C348.1 U22.14(NR)
N20285184: R342.1 R343.1 U22.13(EN)
N20285196: R188.2 U22.12(0P1V)
N20285198: R189.2 U22.11(0P2V)
N20285293: R190.2 U22.10(0P4V)
N20285833: C273.1 C274.2 F1.2 FB16.2 FB44.2 FB45.2 Q4.1(S1) Q4.2(S2) Q4.3(S3) R160.1
N20285975: Q4.4(G) U14.4(GATE)
N20288221: R211.1 R212.1 U26.1(EN)
N20326292: R304.2 U11.6(A5)
N20326294: R305.2 U11.7(A6)
N20326306: R306.2 U11.8(A7)
N20326308: R307.2 U11.9(A8)
N20426571: R217.1 R218.1 U15.6(EN)
N20426573: C281.1 FB21.2 L15.2 R217.2 U15.1(VIN)
N20442953: R219.2 R220.1 U23.7(FB)
N20484075: FB37.1 R224.1 R225.2
N20497118: R330.2 U10.21(ADBUS4)
N20549887: R171.2 R362.1 R363.1
N20651473: D10.1(ANODE) R160.2
N20670192: R312.1 R319.2 U31.20(B1)
N20670214: R313.1 R316.2 U31.18(B2)
N20670236: R314.1 R318.2 U31.17(B3)
N20670258: R315.1 R317.2 U31.16(B4)
N20698575: R328.2 R330.1 U31.15(B5)
N20730230: C318.1 C320.1 FB24.1 L14.1 R355.2 U21.15(IN1) U21.16(IN2) U21.17(IN3)
N20730282: R354.1 R355.1 U21.14(EN)
N20730294: C313.2 C315.1 C317.2 FB53.1 R364.1 U21.1(OUT1) U21.19(OUT2) U21.20(OUT3)
N20730354: C317.1 R254.2 R256.1 U21.3(FB)
N20730369: R334.2 U21.7(200mV)
N20730383: R335.2 U21.6(100mV)
N20730407: R182.2 U21.5(50mV)
N20730507: R180.2 U21.2(SNS)
N20730511: R180.1 R254.1 R364.2 R365.1
N20730545: C326.2 U21.13(NR/SS)
N20737136: R340.1 R341.1 U23.1(EN)
N20804074: FB18.3 R237.2
N20825969: FB53.3 R176.2

Not connected (* = marked no-connect by the designer): J15 4(ID)*; U8 4(NC); U10 22(ADBUS5)* 23(ADBUS6)* 24(ADBUS7)* 33(BDBUS6)* 34(BDBUS7)* 36(SUSPEND)* 43(CDBUS4)* 44(CDBUS5)* 45(CDBUS6)* 46(CDBUS7)* 60(PWREN)*; U12 7(NC)*; U14 1(NC1)* 3(NC3)*; U17 2(PG); U19 2(PG); U21 4(PG) 9(400mV) 10(800mV) 11(1.6V); U22 2(NC1)* 4(6P4V2)* 5(6P4V1)* 6(3P2V)* 9(0P8V)* 17(NC2)* 18(NC3)* 19(NC4)*; U23 2(PG); U24 2(PG); U31 7(A6) 8(A7) 9(A8) 12(B8) 13(B7) 14(B6)

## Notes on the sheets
sheet 11
- VREF = +1.4V
          1A
sheet 12
- 3A
sheet 13
- 3A
- 4A
sheet 14
- 3A
- 3A
- 3A
